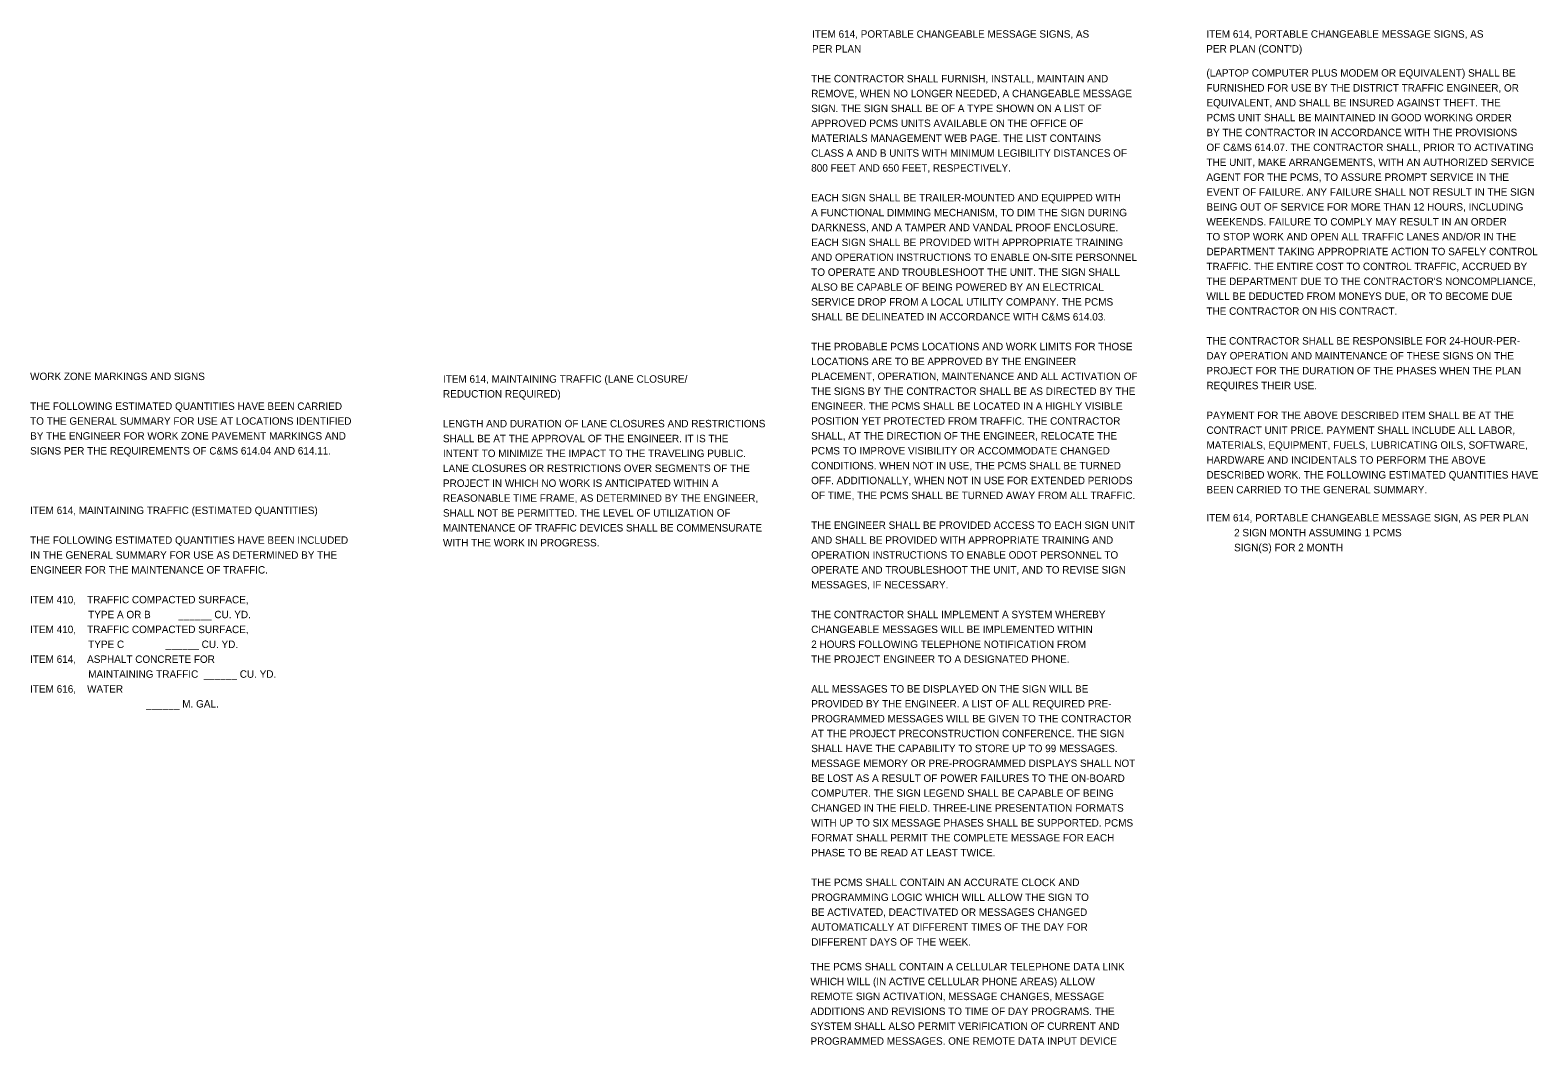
# Model space of a CAD drawing. Extents: x -11.6 to 64.7, y 0 to 22.
# Drawn here: x 36.31 to 64.66, y 2.24 to 21.33 of the extents above; entities that cross this region are included whole.
import ezdxf

# ---------------------------------------------------------------- set-up
doc = ezdxf.new("R2010")
doc.units = 0
doc.layers.add('SH_Text', color=7, linetype='Continuous')

msp = doc.modelspace()

# ---------------------------------------------------------------- texts
at = {"layer": 'SH_Text'}
for s, p in [('ITEM 614, PORTABLE CHANGEABLE MESSAGE SIGNS, AS', (51.012, 21.186)), ('ITEM 614, PORTABLE CHANGEABLE MESSAGE SIGNS, AS', (58.427, 21.186)), ('PER PLAN', (51.012, 20.906)), ("PER PLAN (CONT'D)", (58.427, 20.906)), ('THE CONTRACTOR SHALL FURNISH, INSTALL, MAINTAIN AND', (50.996, 20.346)), ('(LAPTOP COMPUTER PLUS MODEM OR EQUIVALENT) SHALL BE', (58.429, 20.453)), ('REMOVE, WHEN NO LONGER NEEDED, A CHANGEABLE MESSAGE', (50.996, 20.066)), ('FURNISHED FOR USE BY THE DISTRICT TRAFFIC ENGINEER, OR', (58.429, 20.173)), ('SIGN. THE SIGN SHALL BE OF A TYPE SHOWN ON A LIST OF', (50.996, 19.786)), ('EQUIVALENT, AND SHALL BE INSURED AGAINST THEFT. THE', (58.429, 19.893)), ('APPROVED PCMS UNITS AVAILABLE ON THE OFFICE OF', (50.996, 19.506)), ('PCMS UNIT SHALL BE MAINTAINED IN GOOD WORKING ORDER', (58.429, 19.613)), ('MATERIALS MANAGEMENT WEB PAGE. THE LIST CONTAINS', (50.996, 19.226)), ('BY THE CONTRACTOR IN ACCORDANCE WITH THE PROVISIONS', (58.429, 19.333)), ('CLASS A AND B UNITS WITH MINIMUM LEGIBILITY DISTANCES OF', (50.996, 18.946)), ('OF C&MS 614.07. THE CONTRACTOR SHALL, PRIOR TO ACTIVATING', (58.429, 19.053)), ('800 FEET AND 650 FEET, RESPECTIVELY.', (50.996, 18.666)), ('THE UNIT, MAKE ARRANGEMENTS, WITH AN AUTHORIZED SERVICE', (58.429, 18.773)), ('AGENT FOR THE PCMS, TO ASSURE PROMPT SERVICE IN THE', (58.429, 18.493)), ('EACH SIGN SHALL BE TRAILER-MOUNTED AND EQUIPPED WITH', (50.996, 18.106)), ('EVENT OF FAILURE. ANY FAILURE SHALL NOT RESULT IN THE SIGN', (58.429, 18.213)), ('A FUNCTIONAL DIMMING MECHANISM, TO DIM THE SIGN DURING', (50.996, 17.826)), ('BEING OUT OF SERVICE FOR MORE THAN 12 HOURS, INCLUDING', (58.429, 17.933)), ('DARKNESS, AND A TAMPER AND VANDAL PROOF ENCLOSURE.', (50.996, 17.546)), ('WEEKENDS. FAILURE TO COMPLY MAY RESULT IN AN ORDER', (58.429, 17.653)), ('EACH SIGN SHALL BE PROVIDED WITH APPROPRIATE TRAINING', (50.996, 17.266)), ('TO STOP WORK AND OPEN ALL TRAFFIC LANES AND/OR IN THE', (58.429, 17.373)), ('AND OPERATION INSTRUCTIONS TO ENABLE ON-SITE PERSONNEL', (50.996, 16.986)), ('DEPARTMENT TAKING APPROPRIATE ACTION TO SAFELY CONTROL', (58.429, 17.093)), ('TO OPERATE AND TROUBLESHOOT THE UNIT. THE SIGN SHALL', (50.996, 16.706)), ('TRAFFIC. THE ENTIRE COST TO CONTROL TRAFFIC, ACCRUED BY', (58.429, 16.813)), ('ALSO BE CAPABLE OF BEING POWERED BY AN ELECTRICAL', (50.996, 16.426)), ("THE DEPARTMENT DUE TO THE CONTRACTOR'S NONCOMPLIANCE,", (58.429, 16.533)), ('SERVICE DROP FROM A LOCAL UTILITY COMPANY. THE PCMS', (50.996, 16.146)), ('WILL BE DEDUCTED FROM MONEYS DUE, OR TO BECOME DUE', (58.429, 16.253)), ('SHALL BE DELINEATED IN ACCORDANCE WITH C&MS 614.03.', (50.996, 15.866)), ('THE CONTRACTOR ON HIS CONTRACT.', (58.429, 15.973)), ('THE PROBABLE PCMS LOCATIONS AND WORK LIMITS FOR THOSE', (50.996, 15.306)), ('THE CONTRACTOR SHALL BE RESPONSIBLE FOR 24-HOUR-PER-', (58.429, 15.413)), ('LOCATIONS ARE TO BE APPROVED BY THE ENGINEER', (50.996, 15.026)), ('DAY OPERATION AND MAINTENANCE OF THESE SIGNS ON THE', (58.429, 15.133)), ('WORK ZONE MARKINGS AND SIGNS', (36.306, 14.745)), ('ITEM 614, MAINTAINING TRAFFIC (LANE CLOSURE/', (44.07, 14.696)), ('PLACEMENT, OPERATION, MAINTENANCE AND ALL ACTIVATION OF', (50.996, 14.746)), ('PROJECT FOR THE DURATION OF THE PHASES WHEN THE PLAN', (58.429, 14.853)), ('REDUCTION REQUIRED)', (44.07, 14.416)), ('THE SIGNS BY THE CONTRACTOR SHALL BE AS DIRECTED BY THE', (50.996, 14.466)), ('REQUIRES THEIR USE.', (58.429, 14.573)), ('THE FOLLOWING ESTIMATED QUANTITIES HAVE BEEN CARRIED', (36.306, 14.185)), ('ENGINEER. THE PCMS SHALL BE LOCATED IN A HIGHLY VISIBLE', (50.996, 14.186)), ('TO THE GENERAL SUMMARY FOR USE AT LOCATIONS IDENTIFIED', (36.306, 13.905)), ('LENGTH AND DURATION OF LANE CLOSURES AND RESTRICTIONS', (44.07, 13.856)), ('POSITION YET PROTECTED FROM TRAFFIC. THE CONTRACTOR', (50.996, 13.906)), ('PAYMENT FOR THE ABOVE DESCRIBED ITEM SHALL BE AT THE', (58.429, 14.013)), ('BY THE ENGINEER FOR WORK ZONE PAVEMENT MARKINGS AND', (36.306, 13.625)), ('SHALL BE AT THE APPROVAL OF THE ENGINEER. IT IS THE', (44.07, 13.576)), ('SHALL, AT THE DIRECTION OF THE ENGINEER, RELOCATE THE', (50.996, 13.626)), ('CONTRACT UNIT PRICE. PAYMENT SHALL INCLUDE ALL LABOR,', (58.429, 13.733)), ('SIGNS PER THE REQUIREMENTS OF C&MS 614.04 AND 614.11.', (36.306, 13.345)), ('INTENT TO MINIMIZE THE IMPACT TO THE TRAVELING PUBLIC.', (44.07, 13.296)), ('PCMS TO IMPROVE VISIBILITY OR ACCOMMODATE CHANGED', (50.996, 13.346)), ('MATERIALS, EQUIPMENT, FUELS, LUBRICATING OILS, SOFTWARE,', (58.429, 13.453)), ('LANE CLOSURES OR RESTRICTIONS OVER SEGMENTS OF THE', (44.07, 13.016)), ('CONDITIONS. WHEN NOT IN USE, THE PCMS SHALL BE TURNED', (50.996, 13.066)), ('HARDWARE AND INCIDENTALS TO PERFORM THE ABOVE', (58.429, 13.173)), ('PROJECT IN WHICH NO WORK IS ANTICIPATED WITHIN A', (44.07, 12.736)), ('OFF. ADDITIONALLY, WHEN NOT IN USE FOR EXTENDED PERIODS', (50.996, 12.786)), ('DESCRIBED WORK. THE FOLLOWING ESTIMATED QUANTITIES HAVE', (58.429, 12.893)), ('REASONABLE TIME FRAME, AS DETERMINED BY THE ENGINEER,', (44.07, 12.456)), ('OF TIME, THE PCMS SHALL BE TURNED AWAY FROM ALL TRAFFIC.', (50.996, 12.506)), ('BEEN CARRIED TO THE GENERAL SUMMARY.', (58.429, 12.613)), ('ITEM 614, MAINTAINING TRAFFIC (ESTIMATED QUANTITIES)', (36.306, 12.225)), ('SHALL NOT BE PERMITTED. THE LEVEL OF UTILIZATION OF', (44.07, 12.176)), ('ITEM 614, PORTABLE CHANGEABLE MESSAGE SIGN, AS PER PLAN', (58.429, 12.085)), ('MAINTENANCE OF TRAFFIC DEVICES SHALL BE COMMENSURATE', (44.07, 11.896)), ('THE ENGINEER SHALL BE PROVIDED ACCESS TO EACH SIGN UNIT', (50.996, 11.946)), ('          2 SIGN MONTH ASSUMING 1 PCMS', (58.429, 11.805)), ('THE FOLLOWING ESTIMATED QUANTITIES HAVE BEEN INCLUDED', (36.306, 11.665)), ('WITH THE WORK IN PROGRESS.', (44.07, 11.616)), ('AND SHALL BE PROVIDED WITH APPROPRIATE TRAINING AND', (50.996, 11.666)), ('          SIGN(S) FOR 2 MONTH', (58.429, 11.525)), ('IN THE GENERAL SUMMARY FOR USE AS DETERMINED BY THE', (36.306, 11.385)), ('OPERATION INSTRUCTIONS TO ENABLE ODOT PERSONNEL TO', (50.996, 11.386)), ('ENGINEER FOR THE MAINTENANCE OF TRAFFIC.', (36.306, 11.105)), ('OPERATE AND TROUBLESHOOT THE UNIT, AND TO REVISE SIGN', (50.996, 11.106)), ('MESSAGES, IF NECESSARY.', (50.996, 10.826)), ('ITEM 410,    TRAFFIC COMPACTED SURFACE,', (36.306, 10.545)), ('                     TYPE A OR B          ______ CU. YD.', (36.306, 10.265)), ('THE CONTRACTOR SHALL IMPLEMENT A SYSTEM WHEREBY', (50.996, 10.266)), ('ITEM 410,    TRAFFIC COMPACTED SURFACE,', (36.306, 9.985)), ('CHANGEABLE MESSAGES WILL BE IMPLEMENTED WITHIN', (50.996, 9.986)), ('                     TYPE C               ______ CU. YD.', (36.306, 9.705)), ('2 HOURS FOLLOWING TELEPHONE NOTIFICATION FROM', (50.996, 9.706)), ('ITEM 614,    ASPHALT CONCRETE FOR', (36.306, 9.425)), ('THE PROJECT ENGINEER TO A DESIGNATED PHONE.', (50.996, 9.426)), ('                     MAINTAINING TRAFFIC  ______ CU. YD.', (36.306, 9.145)), ('ITEM 616,    WATER', (36.306, 8.865)), ('ALL MESSAGES TO BE DISPLAYED ON THE SIGN WILL BE', (50.996, 8.866)), ('                                          ______ M. GAL.', (36.306, 8.585)), ('PROVIDED BY THE ENGINEER. A LIST OF ALL REQUIRED PRE-', (50.996, 8.586)), ('PROGRAMMED MESSAGES WILL BE GIVEN TO THE CONTRACTOR', (50.996, 8.306)), ('AT THE PROJECT PRECONSTRUCTION CONFERENCE. THE SIGN', (50.996, 8.026)), ('SHALL HAVE THE CAPABILITY TO STORE UP TO 99 MESSAGES.', (50.996, 7.746)), ('MESSAGE MEMORY OR PRE-PROGRAMMED DISPLAYS SHALL NOT', (50.996, 7.466)), ('BE LOST AS A RESULT OF POWER FAILURES TO THE ON-BOARD', (50.996, 7.186)), ('COMPUTER. THE SIGN LEGEND SHALL BE CAPABLE OF BEING', (50.996, 6.906)), ('CHANGED IN THE FIELD. THREE-LINE PRESENTATION FORMATS', (50.996, 6.626)), ('WITH UP TO SIX MESSAGE PHASES SHALL BE SUPPORTED. PCMS', (50.996, 6.346)), ('FORMAT SHALL PERMIT THE COMPLETE MESSAGE FOR EACH', (50.996, 6.066)), ('PHASE TO BE READ AT LEAST TWICE.', (50.996, 5.786)), ('THE PCMS SHALL CONTAIN AN ACCURATE CLOCK AND', (50.996, 5.226)), ('PROGRAMMING LOGIC WHICH WILL ALLOW THE SIGN TO', (50.996, 4.946)), ('BE ACTIVATED, DEACTIVATED OR MESSAGES CHANGED', (50.996, 4.666)), ('AUTOMATICALLY AT DIFFERENT TIMES OF THE DAY FOR', (50.996, 4.386)), ('DIFFERENT DAYS OF THE WEEK.', (50.996, 4.106)), ('THE PCMS SHALL CONTAIN A CELLULAR TELEPHONE DATA LINK', (50.982, 3.641)), ('WHICH WILL (IN ACTIVE CELLULAR PHONE AREAS) ALLOW', (50.982, 3.361)), ('REMOTE SIGN ACTIVATION, MESSAGE CHANGES, MESSAGE', (50.982, 3.081)), ('ADDITIONS AND REVISIONS TO TIME OF DAY PROGRAMS. THE', (50.982, 2.801)), ('SYSTEM SHALL ALSO PERMIT VERIFICATION OF CURRENT AND', (50.982, 2.521)), ('PROGRAMMED MESSAGES. ONE REMOTE DATA INPUT DEVICE', (50.982, 2.241))]:
    msp.add_text(s, height=0.14, dxfattribs=at).set_placement(p)

doc.saveas('drawing.dxf')
